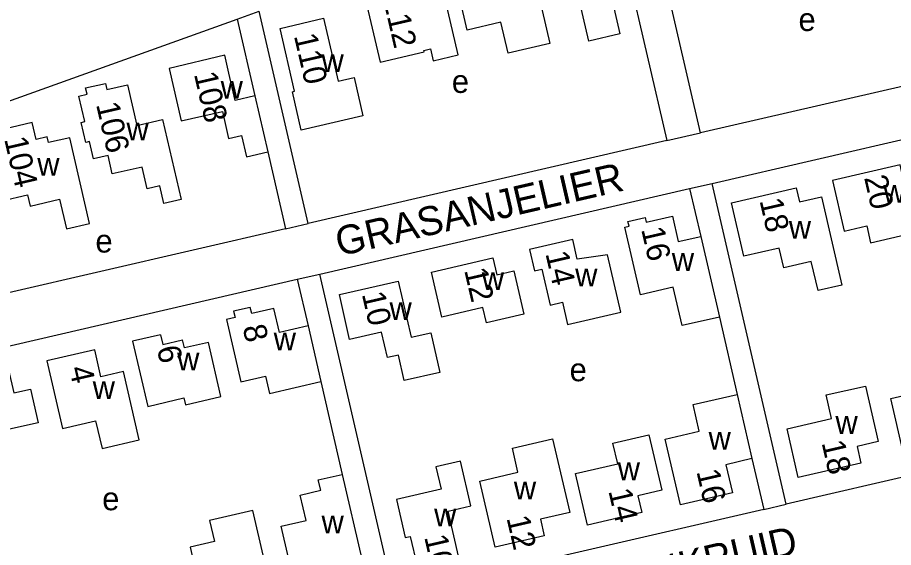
# Model space of a CAD drawing. Extents: x 155696 to 157795, y 382328 to 384028.
# Drawn here: x 157023.6 to 157175.4, y 383614.6 to 383706.4 of the extents above; entities that cross this region are included whole.
import ezdxf

# ---------------------------------------------------------------- set-up
doc = ezdxf.new("R2010")
doc.units = 0
for name, color, linetype in [('BLT_Basislijn', 7, 'Continuous'), ('BLT_Bebouwing', 7, 'Continuous'), ('BLT_Centroide', 7, 'Continuous'), ('BLT_Huisnummer', 7, 'Continuous'), ('BLT_Straatnaam', 7, 'Continuous')]:
    doc.layers.add(name, color=color, linetype=linetype)

msp = doc.modelspace()

# ---------------------------------------------------------------- linework, layer by layer
at = {"layer": 'BLT_Basislijn'}
for p, q in [((157061.7, 383706.08), (157065.49, 383707.44)), ((157061.7, 383706.08), (157064.78, 383692.83)), ((157136.11, 383685.06), (157141.96, 383686.41)), ((157140.08, 383676.74), (157143.98, 383677.64)), ((157070.08, 383669.8), (157073.98, 383670.71)), ((157072.1, 383661.04), (157076, 383661.94)), ((157152.91, 383621.2), (157156.81, 383622.1))]:
    msp.add_line(p, q, dxfattribs=at)
for points in [[(157187.92, 383696.99), (157141.96, 383686.41), (157131.62, 383731.15)], [(157125.93, 383729.11), (157136.11, 383685.06), (157073.98, 383670.71), (157065.49, 383707.44)], [(156999.36, 383683.73), (157061.7, 383706.08)], [(157143.98, 383677.64), (157215.85, 383694.24)], [(157067.01, 383683.09), (157070.08, 383669.8), (157006, 383655)], [(157076, 383661.94), (157140.08, 383676.74), (157142.01, 383668.47)], [(157156.81, 383622.1), (157143.98, 383677.64)], [(157088.83, 383606.4), (157076, 383661.94)], [(157008.02, 383646.23), (157072.1, 383661.04)], [(157072.1, 383661.04), (157073.97, 383652.96)], [(157145.24, 383654.51), (157148.33, 383641.09)], [(157076.2, 383643.32), (157079.91, 383627.27)], [(157228.68, 383638.7), (157156.81, 383622.1)], [(157150.88, 383629.99), (157152.91, 383621.2)], [(157152.91, 383621.2), (157088.83, 383606.4)]]:
    msp.add_lwpolyline(points, dxfattribs=at)
at = {"layer": 'BLT_Bebouwing'}
for p, q in [((157064.78, 383692.83), (157067.01, 383683.09)), ((157079.4, 383658.4), (157089.56, 383660.74)), ((157089.56, 383660.74), (157091.81, 383651)), ((157081.16, 383650.61), (157079.4, 383658.4)), ((157073.97, 383652.96), (157076.2, 383643.32)), ((157048.39, 383651.45), (157043.58, 383650.34)), ((157048.39, 383651.45), (157048.79, 383649.74)), ((157086.72, 383651.87), (157081.16, 383650.61)), ((157087.72, 383647.48), (157086.72, 383651.87)), ((157091.81, 383651), (157095.22, 383651.78)), ((157095.22, 383651.78), (157096.78, 383644.93)), ((157043.58, 383650.34), (157046.19, 383639.04)), ((157048.79, 383649.74), (157052.25, 383650.54)), ((157052.56, 383649.16), (157052.25, 383650.54)), ((157056.7, 383650.12), (157052.56, 383649.16)), ((157058.87, 383640.74), (157056.7, 383650.12)), ((157089.62, 383647.91), (157087.72, 383647.48)), ((157090.61, 383643.53), (157089.62, 383647.91)), ((157096.78, 383644.93), (157090.61, 383643.53)), ((157046.19, 383639.04), (157052.46, 383640.49)), ((157052.46, 383640.49), (157052.73, 383639.32)), ((157052.73, 383639.32), (157058.87, 383640.74)), ((157148.33, 383641.09), (157150.88, 383629.99)), ((157079.91, 383627.27), (157083.3, 383612.59))]:
    msp.add_line(p, q, dxfattribs=at)
for points in [[(157114.1, 383720.62), (157117.85, 383721.48), (157117.73, 383722.02), (157120.18, 383722.58), (157120.31, 383722.05), (157122.02, 383722.44), (157123.14, 383717.62), (157123.89, 383717.8), (157124.38, 383715.65), (157125.13, 383715.82), (157127.97, 383703.53), (157122.6, 383702.29), (157120.65, 383710.75), (157116.6, 383709.81)], [(157098.99, 383715.2), (157104.86, 383716.55), (157104.74, 383717.08), (157108.65, 383717.98), (157109.33, 383715.06), (157112.64, 383715.83), (157115.87, 383701.85), (157108.64, 383700.18), (157107.4, 383705.54), (157101.54, 383704.19)], [(157069.13, 383704.49), (157076.65, 383706.23), (157079.17, 383695.33), (157081.94, 383695.97), (157083.47, 383689.35), (157072.8, 383686.88), (157071.27, 383693.51), (157071.64, 383693.59)], [(157035.44, 383694.17), (157038.88, 383694.97), (157039.14, 383693.89), (157042.7, 383694.72), (157044.34, 383687.69), (157048.76, 383688.71), (157051.97, 383674.83), (157049, 383674.14), (157048.3, 383677.22), (157046.08, 383676.7), (157045.22, 383680.46), (157040.06, 383679.28), (157039.34, 383682.45), (157036.8, 383681.87), (157036.1, 383684.88), (157035.45, 383684.73), (157034.65, 383688.19), (157035.31, 383688.34), (157034.28, 383692.76), (157035.7, 383693.09)], [(157032.69, 383685.56), (157028.99, 383684.7), (157028.77, 383685.68), (157026.88, 383685.24), (157026.2, 383688.16), (157018.84, 383686.46), (157020.05, 383681.2), (157019.43, 383681.06), (157020.91, 383674.62), (157025.39, 383675.66), (157025.84, 383673.71), (157030.93, 383674.89), (157032.11, 383669.78), (157036.12, 383670.71)], [(157182.57, 383669.94), (157180.54, 383678.71), (157177.21, 383677.94), (157176.53, 383680.86), (157164.84, 383678.16), (157166.87, 383669.39), (157170.76, 383670.29), (157171.44, 383667.37)], [(157147.33, 383674.3), (157158.54, 383676.9), (157159.12, 383674.43), (157162.91, 383675.3), (157166.44, 383660.03), (157162.36, 383659.1), (157161.16, 383664.12), (157156.38, 383663.02), (157155.59, 383666.42), (157149.48, 383665.03)], [(157095.34, 383662.3), (157106.01, 383664.76), (157106.69, 383661.84), (157109.61, 383662.51), (157111.34, 383655.01), (157104.88, 383653.51), (157104.27, 383656.15), (157097.14, 383654.5)], [(157186.97, 383650.88), (157190.24, 383636.53), (157186.3, 383635.6), (157186.63, 383634.1), (157184.83, 383633.7), (157184.69, 383634.32), (157183.07, 383633.94), (157183.21, 383633.34), (157183.43, 383632.35), (157177.12, 383630.89), (157174.93, 383640.42), (157180.4, 383641.69), (157179.74, 383644.59), (157181.88, 383645.08), (157180.87, 383649.47), (157180.33, 383651.85), (157186.42, 383653.25)], [(157011.36, 383642.9), (157022.07, 383645.37), (157023, 383641.38), (157025.87, 383642.04), (157027.22, 383636.2), (157017.02, 383633.94), (157016.48, 383636.28), (157013.07, 383635.49)], [(157170.54, 383642.56), (157172.73, 383632.93), (157169.11, 383632.11), (157169.75, 383629.19), (157158.87, 383626.73), (157156.96, 383635.16), (157164.66, 383636.94), (157163.72, 383641.01)], [(157133.04, 383634.1), (157135.26, 383624.52), (157131.13, 383623.56), (157131.8, 383620.64), (157122.37, 383618.47), (157120.3, 383627.41), (157127.62, 383629.1), (157126.79, 383632.65)], [(157109.37, 383631.78), (157116.31, 383633.41), (157119.3, 383620.66), (157114.25, 383619.48), (157114.9, 383616.61), (157106.38, 383614.64), (157103.73, 383626.09), (157110.34, 383627.64)], [(157100.36, 383629.56), (157096.13, 383628.59), (157097.03, 383624.7), (157089.29, 383622.91), (157090.81, 383616.32), (157091.69, 383616.52), (157092.86, 383611.43), (157100.06, 383613.1), (157098.26, 383620.89), (157102.16, 383621.79)]]:
    msp.add_lwpolyline(points, close=True, dxfattribs=at)
for points in [[(157096.57, 383714.54), (157092.27, 383713.55), (157092.51, 383712.52), (157083.72, 383710.49), (157086.45, 383698.66), (157094.07, 383700.42), (157094.02, 383700.65), (157095.19, 383700.92), (157095.66, 383698.89), (157099.96, 383699.89), (157096.57, 383714.54)], [(157064.78, 383692.83), (157061.37, 383692.02), (157060.25, 383696.72), (157059.57, 383699.83), (157049.9, 383697.56), (157052, 383688.45), (157059.16, 383690.1), (157060.2, 383685.42), (157062.43, 383685.93), (157063.29, 383682.25), (157067.01, 383683.09)], [(157145.24, 383654.51), (157138.77, 383653.05), (157137.25, 383659.67), (157131.56, 383658.37), (157128.86, 383670.07), (157129.59, 383670.24), (157129.4, 383671.06), (157132.38, 383671.75), (157132.57, 383670.91), (157137.1, 383671.95), (157138.12, 383667.57), (157142.01, 383668.47)], [(157118.95, 383653.2), (157128.16, 383655.32), (157125.86, 383665.28), (157120.61, 383664.52), (157119.82, 383667.95), (157112.33, 383666.22), (157113.19, 383662.48), (157114.48, 383662.78), (157115.92, 383656.56), (157118.06, 383657.06), (157118.95, 383653.2)], [(157142.01, 383668.47), (157145.24, 383654.51)], [(157073.97, 383652.96), (157069.04, 383651.82), (157068.07, 383656), (157064.22, 383655.11), (157063.97, 383656.18), (157061.08, 383655.51), (157061.33, 383654.44), (157059.83, 383654.1), (157062.33, 383643.28), (157066.62, 383644.27), (157067.31, 383641.27), (157076.2, 383643.32)], [(157041.99, 383645.05), (157038.09, 383644.15), (157037.01, 383648.82), (157028.73, 383646.91), (157031.43, 383635.22), (157037.18, 383636.55), (157038.28, 383631.77), (157044.71, 383633.26), (157041.99, 383645.05)], [(157150.88, 383629.99), (157146.38, 383628.93), (157147.48, 383624.05), (157138.47, 383621.98), (157135.85, 383633.37), (157141.74, 383634.72), (157140.68, 383639.34), (157148.33, 383641.09)], [(157083.3, 383612.59), (157079.99, 383611.83), (157080.59, 383609.14), (157080.07, 383609.01), (157080.2, 383608.46), (157072.04, 383606.6), (157069.34, 383618.31), (157073.62, 383619.3), (157072.61, 383623.68), (157076.17, 383624.5), (157075.75, 383626.31), (157079.91, 383627.27)], [(157064.42, 383604.86), (157062.83, 383611.72), (157066.37, 383612.54), (157064.41, 383621), (157056.92, 383619.26), (157057.76, 383615.62), (157053.58, 383614.65), (157056.28, 383602.98), (157059.13, 383603.64), (157059.3, 383602.89), (157061.74, 383603.45), (157061.57, 383604.2), (157064.42, 383604.86)]]:
    msp.add_lwpolyline(points, dxfattribs=at)

# ---------------------------------------------------------------- texts
at = {"layer": 'BLT_Centroide'}
for s, p in [('e', (157158.94, 383704.03)), ('w', (157076.3, 383696.92)), ('e', (157098.88, 383693.31)), ('w', (157058.83, 383692.33)), ('w', (157042.52, 383685.09)), ('w', (157027.06, 383678.97)), ('w', (157173.62, 383674.28)), ('w', (157157.26, 383668.09)), ('e', (157037.14, 383665.67)), ('w', (157136.99, 383662.5)), ('w', (157120.25, 383659.81)), ('w', (157104.07, 383659.19)), ('w', (157088.09, 383654)), ('w', (157068.02, 383648.72)), ('w', (157051.29, 383645.25)), ('e', (157119.29, 383643.39)), ('w', (157036.66, 383640.31)), ('w', (157165.34, 383634.28)), ('w', (157143.36, 383631.55)), ('w', (157127.61, 383626.25)), ('w', (157109.63, 383622.93)), ('e', (157038.32, 383621.05)), ('w', (157095.81, 383618.28)), ('w', (157076.31, 383617.05))]:
    msp.add_text(s, height=4, dxfattribs=at).set_placement(p)
at = {"layer": 'BLT_Huisnummer'}
for s, rotation, p in [('112', 283.0079, (157086.96, 383709.49)), ('110', 283.0079, (157071.51, 383703.2)), ('108', 283.0079, (157054.19, 383696.57)), ('106', 283.0079, (157037.23, 383691.32)), ('104', 283.0079, (157021.32, 383685.32)), ('20', 283.0059, (157170.29, 383678.65)), ('18', 283.0075, (157152.17, 383674.68)), ('16', 283.0059, (157131.67, 383669.7)), ('14', 283.0074, (157115.08, 383665.5)), ('12', 283.007, (157101.01, 383662.62)), ('10', 283.0069, (157083.27, 383658.49)), ('8', 283.0069, (157062.61, 383652.76)), ('6', 283.0075, (157047.74, 383649.12)), ('4', 283.007, (157032.56, 383645.63)), ('18', 283.0075, (157162.92, 383632.75)), ('16', 283.0046, (157141.24, 383627.76)), ('14', 283.0072, (157125.99, 383624.41)), ('12', 283.0027, (157108.34, 383619.71)), ('10', 283.0069, (157094.08, 383616.42))]:
    msp.add_text(s, height=4, rotation=rotation, dxfattribs=at).set_placement(p)
at = {"layer": 'BLT_Straatnaam'}
for s, rotation, p in [('GRASANJELIER', 13.007, (157079.38, 383665)), ('GRASFONTEINKRUID', 13.0072, (157091.76, 383597.99))]:
    msp.add_text(s, height=5, rotation=rotation, dxfattribs=at).set_placement(p)

doc.saveas('drawing.dxf')
